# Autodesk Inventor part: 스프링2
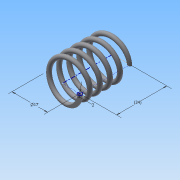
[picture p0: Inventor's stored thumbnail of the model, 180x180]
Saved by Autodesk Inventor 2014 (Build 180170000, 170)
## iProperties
Created: 2016-01
Part Number: 스프링2
Material: 강철, 탄소
Document SubType Name: Modeling
Designer: Administrator
Density: 7.87 g/cm^3
Appearance: 반연마
Mass: 6.44239 g
Surface Area: 16.6857 cm^2
Volume: 0.818602 cm^3
Author: Administrator
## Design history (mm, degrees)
sketch "스케치1"
  geometry: L1 (0, 0)-(8.5, 0); L2 (8.5, 0)-(8.5, 17.5); L3 (8.5, 17.5)-(0, 17.5); L4 (0, 17.5)-(0, 0); C1 r 1 at (8.5, 0)
  constraints: 8 end point, 2 parallel, 1 centre point, 1 coincident, 1 horizontal, 1 perpendicular
  dimensions: "d0" = 17.5 distance of L1.end L2.end (derived); "d1" = 17 diameter of L2 L4; "d2" = 2 diameter of C1
feature "코일1" sketch "스케치1" pitch "d3" = 10; turns "d5" = 5; dims "d4" = 17.5 (= d0), "d6" = 0, angle "d7" = 90 deg, angle "d8" = 90 deg, "d9" = 0, "d10" = 0
node "작업 평면2"
  node "작업 평면1"
sketch "스케치2"
  geometry: L1 (-9.5, 0)-(-7.5, 0) reference; 1 further point
  constraints: 1 horizontal alignment
extrude "돌출1" cut sketch "스케치2" distance "d13" = 10; taper "d14" = 0 deg
sketch "스케치3"
  geometry: L1 (-7.5, 0)-(-9.5, 0) reference; 1 further point
  constraints: 1 horizontal alignment
extrude "돌출2" cut sketch "스케치3" distance "d15" = 10; taper "d16" = 0 deg
node "솔리드1"
node "절단 모서리 투영1"
node "절단 모서리 투영2"
other parameters: "d11" = 0, "d12" = 17.5 (= d0)
